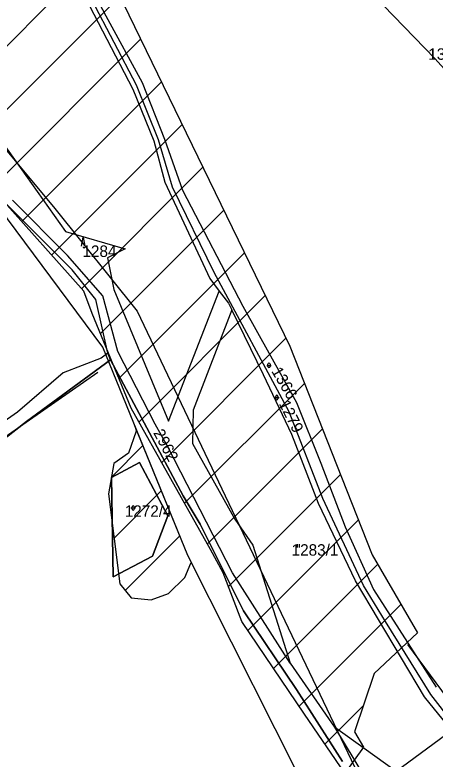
# Model space of a CAD drawing. Extents: x -564810 to -550519, y -1045831 to -1034011.
# Drawn here: x -554393.2 to -554205.9, y -1038538.6 to -1038207.3 of the extents above; entities that cross this region are included whole.
import ezdxf

# ---------------------------------------------------------------- set-up
doc = ezdxf.new("R2010")
doc.units = 0
for name, color, linetype in [('Biokoridory', 7, 'Continuous'), ('Interakční prvky', 7, 'Continuous'), ('KN stav', 7, 'Continuous'), ('Lesní porost', 7, 'Continuous'), ('Parcelní čísla', 7, 'Continuous'), ('STG', 7, 'Continuous'), ('zamokř ploch', 7, 'Continuous')]:
    doc.layers.add(name, color=color, linetype=linetype)

msp = doc.modelspace()

# ---------------------------------------------------------------- linework, layer by layer
at = {"layer": 'Biokoridory'}
for points in [[(-554166.15, -1038675.89), (-554257.77, -1038563.66), (-554316.17, -1038448), (-554353.97, -1038355.23), (-554404.36, -1038287.66), (-554483.38, -1038224.68), (-554553.23, -1038193.76), (-554605.91, -1038189.18), (-554631.11, -1038158.26), (-554628.82, -1038068.93)], [(-554606.72, -1038072.44), (-554612.45, -1038142.3), (-554588.4, -1038159.48), (-554532.28, -1038162.91), (-554465.86, -1038200.71), (-554410.89, -1038251.1), (-554375.39, -1038293.47), (-554338.74, -1038339.28), (-554300.95, -1038418.3), (-554240.25, -1038545.42), (-554153.22, -1038648.49)]]:
    msp.add_lwpolyline(points, dxfattribs=at)
at = {"layer": 'Interakční prvky'}
for p, q in [((-554480.8, -1038452.95), (-554356.15, -1038366.32)), ((-554218.18, -1038487.56), (-554113.21, -1038629.98))]:
    msp.add_line(p, q, dxfattribs=at)
at = {"layer": 'KN stav'}
for p, q in [((-554376.1, -1038172.04), (-554340.55, -1038240.46)), ((-554370.29, -1038173.56), (-554352.65, -1038207.75)), ((-554339.02, -1038238.68), (-554358.87, -1038200.47)), ((-554352.65, -1038207.75), (-554336.51, -1038237.44)), ((-554336.51, -1038237.44), (-554326.5, -1038262.63)), ((-554340.55, -1038240.46), (-554331.32, -1038263.46)), ((-554329.18, -1038262.95), (-554339.02, -1038238.68)), ((-554402.53, -1038258.82), (-554370.6, -1038303.77)), ((-554331.32, -1038263.46), (-554326.32, -1038281.85)), ((-554322.95, -1038283.95), (-554329.18, -1038262.95)), ((-554326.5, -1038262.63), (-554318.43, -1038285.42)), ((-554367.67, -1038320.84), (-554414.5, -1038274.15)), ((-554326.32, -1038281.85), (-554306.23, -1038324.69)), ((-554304.42, -1038322.07), (-554322.95, -1038283.95)), ((-554318.43, -1038285.42), (-554291.63, -1038336.99)), ((-554369.66, -1038314.45), (-554394.3, -1038289.81)), ((-554370.6, -1038303.77), (-554343.96, -1038311.46)), ((-554343.96, -1038311.46), (-554351.94, -1038315.4)), ((-554353.92, -1038332.44), (-554369.66, -1038314.45)), ((-554351.94, -1038315.4), (-554349.1, -1038329.54)), ((-554357.14, -1038334), (-554367.67, -1038320.84)), ((-554270.89, -1038383.98), (-554304.42, -1038322.07)), ((-554306.23, -1038324.69), (-554302.13, -1038330.34)), ((-554349.1, -1038329.54), (-554324.79, -1038388.2)), ((-554324.79, -1038388.2), (-554302.13, -1038330.34)), ((-554302.13, -1038330.34), (-554298, -1038335.59)), ((-554347.37, -1038357.16), (-554353.92, -1038332.44)), ((-554351.77, -1038357.97), (-554357.14, -1038334)), ((-554298, -1038335.59), (-554296.54, -1038338.59)), ((-554291.63, -1038336.99), (-554267.65, -1038379.89)), ((-554296.54, -1038338.59), (-554313.66, -1038383.28)), ((-554282.44, -1038367.59), (-554296.54, -1038338.59)), ((-554330.69, -1038389.49), (-554347.37, -1038357.16)), ((-554354.7, -1038360.07), (-554371.7, -1038366.69)), ((-554351.77, -1038357.97), (-554354.7, -1038360.07)), ((-554350.52, -1038360.86), (-554351.77, -1038357.97)), ((-554350.52, -1038360.86), (-554388, -1038388.29)), ((-554388, -1038388.29), (-554350.52, -1038360.86)), ((-554318.12, -1038421.37), (-554350.52, -1038360.86)), ((-554350.52, -1038360.86), (-554318.12, -1038421.37)), ((-554371.7, -1038366.69), (-554392.06, -1038384.18)), ((-554269.71, -1038394.14), (-554282.44, -1038367.59)), ((-554267.65, -1038379.89), (-554256.78, -1038406.89)), ((-554313.66, -1038383.28), (-554314.03, -1038398.07)), ((-554392.06, -1038384.18), (-554418.95, -1038403.02)), ((-554255.97, -1038422.58), (-554270.89, -1038383.98)), ((-554388, -1038388.29), (-554419.77, -1038413.11)), ((-554419.77, -1038413.11), (-554388, -1038388.29)), ((-554324.99, -1038399.65), (-554330.69, -1038389.49)), ((-554257.86, -1038424.81), (-554269.71, -1038394.14)), ((-554296.22, -1038455.63), (-554324.99, -1038399.65)), ((-554314.03, -1038398.07), (-554295.19, -1038431.73)), ((-554337.66, -1038406.55), (-554350.08, -1038413.27)), ((-554350.08, -1038413.27), (-554337.66, -1038406.55)), ((-554324.98, -1038430.31), (-554337.66, -1038406.55)), ((-554337.66, -1038406.55), (-554324.98, -1038430.31)), ((-554256.78, -1038406.89), (-554246.01, -1038435.24)), ((-554350.08, -1038413.27), (-554349.43, -1038457.44)), ((-554349.43, -1038457.44), (-554350.08, -1038413.27)), ((-554310.55, -1038433.97), (-554318.12, -1038421.37)), ((-554318.12, -1038421.37), (-554310.55, -1038433.97)), ((-554237.85, -1038461.27), (-554255.97, -1038422.58)), ((-554241.44, -1038459.25), (-554257.86, -1038424.81)), ((-554331.85, -1038448.22), (-554324.98, -1038430.31)), ((-554324.98, -1038430.31), (-554331.85, -1038448.22)), ((-554295.19, -1038431.73), (-554287.14, -1038443.39)), ((-554291.36, -1038472.6), (-554310.55, -1038433.97)), ((-554310.55, -1038433.97), (-554291.36, -1038472.6)), ((-554246.01, -1038435.24), (-554233.38, -1038463.12)), ((-554287.14, -1038443.39), (-554270.55, -1038495.9)), ((-554349.43, -1038457.44), (-554331.85, -1038448.22)), ((-554331.85, -1038448.22), (-554349.43, -1038457.44)), ((-554270.55, -1038495.9), (-554296.22, -1038455.63)), ((-554210.62, -1038510.85), (-554241.44, -1038459.25)), ((-554228.03, -1038477.4), (-554237.85, -1038461.27)), ((-554233.38, -1038463.12), (-554205.41, -1038506.5)), ((-554267.66, -1038507.58), (-554291.36, -1038472.6)), ((-554291.36, -1038472.6), (-554267.66, -1038507.58)), ((-554207.86, -1038509.88), (-554228.03, -1038477.4)), ((-554270.55, -1038495.9), (-554250.75, -1038524.36)), ((-554247.21, -1038539.71), (-554267.66, -1038507.58)), ((-554267.66, -1038507.58), (-554247.21, -1038539.71)), ((-554198.53, -1038525.91), (-554210.62, -1038510.85)), ((-554171.11, -1038556.96), (-554207.86, -1038509.88)), ((-554250.75, -1038524.36), (-554233.84, -1038552.12)), ((-554223.22, -1038544.07), (-554250.75, -1038524.36)), ((-554198.53, -1038525.91), (-554223.22, -1038544.07))]:
    msp.add_line(p, q, dxfattribs=at)
at = {"layer": 'Lesní porost'}
for p, q in [((-554434.91, -1038259.27), (-554355.61, -1038179.97)), ((-554419.08, -1038271.73), (-554346.36, -1038199)), ((-554403.96, -1038284.88), (-554337.11, -1038218.04)), ((-554390.18, -1038299.39), (-554327.87, -1038237.08)), ((-554376.82, -1038314.31), (-554318.62, -1038256.11)), ((-554363.45, -1038329.23), (-554309.37, -1038275.15)), ((-554355.07, -1038349.13), (-554300.13, -1038294.19)), ((-554346.82, -1038369.17), (-554290.88, -1038313.23)), ((-554337.92, -1038388.55), (-554281.63, -1038332.26)), ((-554327.72, -1038406.64), (-554272.39, -1038351.3)), ((-554317.53, -1038424.73), (-554264.14, -1038371.34)), ((-554339.72, -1038390.19), (-554339.2, -1038392.63)), ((-554339.2, -1038392.63), (-554342.47, -1038402.42)), ((-554307.34, -1038442.83), (-554256.12, -1038391.6)), ((-554350.17, -1038413.13), (-554336.11, -1038399.06)), ((-554342.47, -1038402.42), (-554349.12, -1038407.06)), ((-554349.12, -1038407.06), (-554351.45, -1038420.5)), ((-554297.97, -1038461.74), (-554248.09, -1038411.86)), ((-554348.96, -1038440.2), (-554327.92, -1038419.16)), ((-554351.45, -1038420.5), (-554346.38, -1038460.64)), ((-554289.34, -1038481.4), (-554240.07, -1038432.12)), ((-554344.01, -1038463.54), (-554319.73, -1038439.26)), ((-554317.38, -1038457.75), (-554314.81, -1038451.45)), ((-554314.81, -1038451.45), (-554314.53, -1038451.25)), ((-554277.91, -1038498.24), (-554231.49, -1038451.83)), ((-554324.73, -1038464.92), (-554317.38, -1038457.75)), ((-554346.38, -1038460.64), (-554341.39, -1038466.74)), ((-554332.44, -1038467.67), (-554324.73, -1038464.92)), ((-554341.39, -1038466.74), (-554332.44, -1038467.67)), ((-554266.47, -1038515.09), (-554221.12, -1038469.74)), ((-554255, -1038531.9), (-554237.99, -1038514.9))]:
    msp.add_line(p, q, dxfattribs=at)
for points in [[(-554350.14, -1038191.22), (-554270.7, -1038354.77), (-554247.59, -1038413.13), (-554233.94, -1038447.61), (-554213.84, -1038482.32), (-554233.11, -1038500.48), (-554241.91, -1038526.46), (-554237.9, -1038533.22), (-554246.14, -1038544.85), (-554264.14, -1038518.53), (-554292.07, -1038477.38), (-554300.29, -1038455.61), (-554305.98, -1038445.25), (-554341.41, -1038382.34), (-554358.69, -1038340.31), (-554362.52, -1038330.27), (-554400.47, -1038287.91), (-554423.68, -1038267.73), (-554446.38, -1038250.63), (-554481.33, -1038228.53), (-554507.22, -1038209.19), (-554536.4, -1038206)], [(-554314.53, -1038451.25), (-554316.17, -1038448), (-554339.72, -1038390.19)]]:
    msp.add_lwpolyline(points, dxfattribs=at)
at = {"layer": 'STG'}
msp.add_lwpolyline([(-553875.31, -1038175.25), (-553855.1, -1038212), (-553825.71, -1038278.16), (-553827.54, -1038324.1), (-553845.92, -1038346.15), (-553878.98, -1038360.85), (-553992.88, -1038347.99), (-554066.37, -1038342.47), (-554136.18, -1038303.88), (-554205.99, -1038226.71), (-554261.1, -1038169.74)], dxfattribs=at)
at = {"layer": 'zamokř ploch'}
for p, q in [((-554280.97, -1038363.33), (-554278.97, -1038363.33)), ((-554280.47, -1038363.83), (-554280.47, -1038362.83)), ((-554279.47, -1038362.83), (-554279.47, -1038363.83)), ((-554277.45, -1038377.66), (-554275.45, -1038377.66)), ((-554276.95, -1038378.16), (-554276.95, -1038377.16)), ((-554275.95, -1038377.16), (-554275.95, -1038378.16)), ((-554340.98, -1038427.31), (-554340.98, -1038426.31)), ((-554339.98, -1038426.31), (-554339.98, -1038427.31)), ((-554341.48, -1038426.81), (-554339.48, -1038426.81)), ((-554267.43, -1038442.89), (-554267.43, -1038444.39)), ((-554266.43, -1038442.89), (-554266.43, -1038444.39))]:
    msp.add_line(p, q, dxfattribs=at)
for points in [[(-554363.46, -1038310.31), (-554362.76, -1038306.31), (-554361.96, -1038310.31)], [(-554362.76, -1038310.6), (-554362.76, -1038310.81), (-554361.96, -1038310.81)]]:
    msp.add_lwpolyline(points, dxfattribs=at)
for centre, start, end in [((-554279.97, -1038362.83), 0, 180), ((-554279.97, -1038363.83), 180, 0), ((-554276.46, -1038377.16), 0, 180), ((-554276.46, -1038378.16), 180, 0), ((-554340.48, -1038426.31), 0, 180), ((-554340.48, -1038427.31), 180, 0)]:
    msp.add_arc(centre, 0.5, start, end, dxfattribs=at)

# ---------------------------------------------------------------- texts
at = {"layer": 'Parcelní čísla'}
for s, p in [('1367', (-554208.95, -1038227.32)), ('1284', (-554363.07, -1038315.07)), ('1272/4', (-554344.21, -1038430.75)), ('1283/1', (-554269.87, -1038448.04))]:
    msp.add_text(s, height=5.1, dxfattribs=at).set_placement(p)
for s, rotation, p in [('1366', 300.3355, (-554279.04, -1038365.9)), ('1279', 296.5461, (-554275.66, -1038380.33)), ('2962', 297.8664, (-554331.62, -1038393.31))]:
    msp.add_text(s, height=5.1, rotation=rotation, dxfattribs=at).set_placement(p)

doc.saveas('drawing.dxf')
